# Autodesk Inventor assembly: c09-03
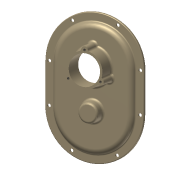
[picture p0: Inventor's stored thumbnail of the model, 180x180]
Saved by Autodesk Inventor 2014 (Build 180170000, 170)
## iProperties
Created: 2010-12
Part Number: c09-03
Document SubType Name: Assembly
Designer: Thom Tremblay
Author: Thom Tremblay
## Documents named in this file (2)
- C:\Inventor 2014 Essentials\Assemblies\Chapter 09\c09-03.iam
- C:\Inventor 2014 Essentials\Parts\Chapter 09\c09-10.ipt
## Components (1 placed, 1 different names)
1. c09-10:1
